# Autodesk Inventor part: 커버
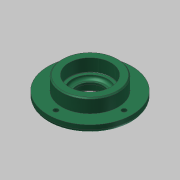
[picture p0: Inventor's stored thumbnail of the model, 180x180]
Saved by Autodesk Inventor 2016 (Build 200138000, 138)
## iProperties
Company: 한국ATC센터
Created: 2014-10
Part Number: 커버
Document SubType Name: Modeling
Designer: KYOUNG IL JANG
Density: 2.71 g/cm^3
Mass: 121.214 g
Surface Area: 161.165 cm^2
Volume: 44.7286 cm^3
Material: 알루미늄 6061
Appearance: 알루미늄 - 평지
Author: KYOUNG IL JANG
Revision Number: 1
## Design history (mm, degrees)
sketch "스케치1"
  geometry: C1 r 41 at (0, 0); 1 further point
  constraints: 1 centre point, 1 coincident
  dimensions: "d0" = 82 diameter of C1
extrude "돌출1" new body sketch "스케치1" distance "d1" = 7; taper "d2" = 0 deg
sketch "스케치2"
  geometry: C1 r 27 at (0, 0); 1 further point
  constraints: 1 centre point, 1 coincident
  dimensions: "d3" = 54 diameter of C1
extrude "돌출2" join sketch "스케치2" distance "d4" = 13; taper "d5" = 0 deg
sketch "스케치3"
  geometry: C1 r 20 at (0, 0); 1 further point
  constraints: 1 centre point, 1 coincident
  dimensions: "d6" = 40 diameter of C1
extrude "돌출3" join sketch "스케치3" distance "d7" = 5; taper "d8" = 0 deg
hole "구멍1" diameter "d11" = 25; stored, may be unused: countersink angle "d15" = 90 deg, drill point angle "d17" = 118 deg; dims "d9" = 10, "d10" = 10, "d12" = 6, "d13" = 32, "d14" = 8.3, "d16" = 8
hole "구멍2" diameter "d20" = 34; stored, may be unused: countersink angle "d24" = 90 deg, drill point angle "d26" = 0 deg; dims "d18" = 10, "d19" = 10, "d21" = 6, "d22" = 40, "d23" = 12, "d25" = 3
fillet "모깎기2" dims "d34" = 3
fillet "모깎기1" dims "d27" = 0.3
chamfer "모따기1" distance "d28" = 1; stored, may be unused: second distance "d29" = 2, angle "d30" = 45 deg
chamfer "모따기2" distance "d31" = 1.2; stored, may be unused: second distance "d32" = 2, angle "d33" = 30 deg
sketch "스케치4" dims "d35" = 66
  geometry: 3 further points
  constraints: 2 horizontal alignment, 1 coincident, 2 other
hole "구멍3" sketch "스케치4" at (33, 0) diameter "d36" = 4.5; stored, may be unused: countersink angle "d40" = 90 deg, drill point angle "d42" = 118 deg; dims "d37" = 6, "d38" = 8, "d39" = 4.4, "d41" = 13
node "솔리드1"
pattern_circular "원형 패턴1" dims angle "d44" = 360 deg
